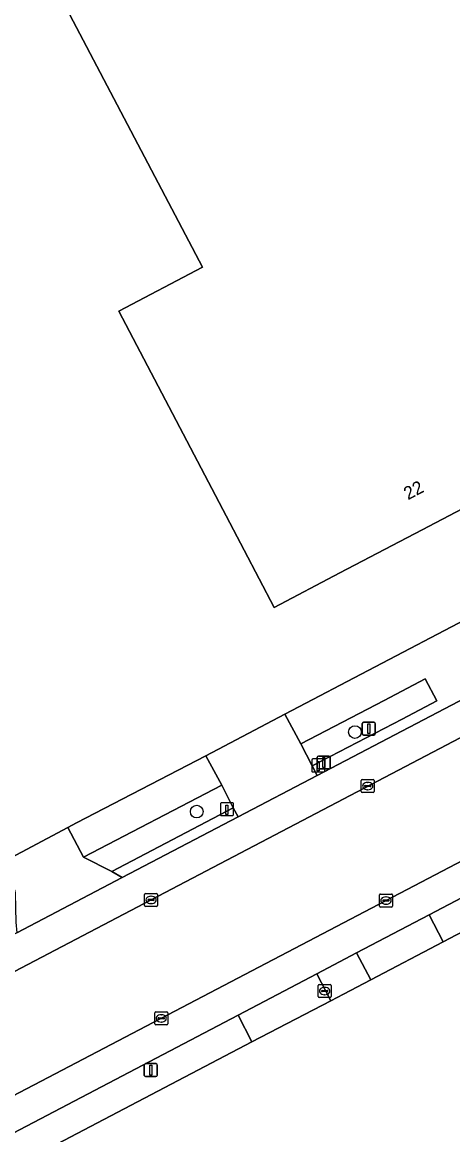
# Model space of a CAD drawing. Extents: x 157692 to 159674, y 381452 to 383291.
# Drawn here: x 158344.4 to 158377.6, y 381842.8 to 381928.6 of the extents above; entities that cross this region are included whole.
import ezdxf

# ---------------------------------------------------------------- set-up
doc = ezdxf.new("R2010")
doc.units = 0
for name, color, linetype in [('IMGEO_Boom', 7, 'Continuous'), ('IMGEO_Brandkraan', 7, 'Continuous'), ('IMGEO_Erf', 7, 'Continuous'), ('IMGEO_Groenvoorziening', 7, 'Continuous'), ('IMGEO_Kolk', 7, 'Continuous'), ('IMGEO_Lichtmast', 7, 'Continuous'), ('IMGEO_Paal', 7, 'Continuous'), ('IMGEO_Pand', 7, 'Continuous'), ('IMGEO_Pand_nummerreeks', 7, 'Continuous'), ('IMGEO_Parkeervlak_open', 7, 'Continuous'), ('IMGEO_Rijbaan_lokaal_gesloten', 7, 'Continuous'), ('IMGEO_Rijbaan_lokaal_open', 7, 'Continuous'), ('IMGEO_Verkeersbordpaal', 7, 'Continuous'), ('IMGEO_Voetpad_open', 7, 'Continuous')]:
    doc.layers.add(name, color=color, linetype=linetype)

msp = doc.modelspace()

# ---------------------------------------------------------------- linework, layer by layer
at = {"layer": 'IMGEO_Boom'}
for centre in [(158370.043, 381873.88), (158357.856, 381867.748)]:
    msp.add_circle(centre, 0.489, dxfattribs=at)
at = {"layer": 'IMGEO_Brandkraan'}
for p, q in [((158367.213, 381853.487), (158367.213, 381854.339)), ((158367.288, 381854.413), (158368.14, 381854.413)), ((158367.515, 381853.956), (158367.913, 381853.956)), ((158367.701, 381854.193), (158367.726, 381854.193)), ((158368.214, 381854.339), (158368.214, 381853.487)), ((158368.14, 381853.413), (158367.288, 381853.413)), ((158367.472, 381853.907), (158367.472, 381853.919)), ((158367.91, 381853.87), (158367.512, 381853.87)), ((158367.724, 381853.633), (158367.699, 381853.633)), ((158367.956, 381853.919), (158367.956, 381853.907))]:
    msp.add_line(p, q, dxfattribs=at)
for points in [[(158367.213, 381853.487), (158367.213, 381854.339)], [(158367.288, 381854.413), (158368.14, 381854.413)], [(158368.214, 381854.339), (158368.214, 381853.487)], [(158368.14, 381853.413), (158367.288, 381853.413)]]:
    msp.add_lwpolyline(points, dxfattribs=at)
for centre, radius, start, end in [((158367.29, 381854.337), 0.0765, 91.55205, 178.44795), ((158367.29, 381854.337), 0.0765, 91.55205, 178.44795), ((158367.512, 381853.916), 0.0403, 85.87752, 175.75265), ((158367.917, 381853.918), 0.0386, 1.73085, 96.63898), ((158368.138, 381854.337), 0.0765, 1.55205, 88.44795), ((158368.138, 381854.337), 0.0765, 1.55205, 88.44795), ((158367.29, 381853.489), 0.0765, 181.55205, 268.44795), ((158367.29, 381853.489), 0.0765, 181.55205, 268.44795), ((158367.509, 381853.906), 0.0366, 178.93798, 274.71019), ((158367.913, 381853.913), 0.043, 264.86636, 352.45326), ((158368.138, 381853.489), 0.0765, 271.55205, 358.44795), ((158368.138, 381853.489), 0.0765, 271.55205, 358.44795)]:
    msp.add_arc(centre, radius, start, end, dxfattribs=at)
for centre, major_axis, ratio, start_param, end_param in [((158367.7, 381853.913), (-0.387, 0.002), 0.722429, 4.712389, 7.853982), ((158367.725, 381853.913), (-0.39, 0.002), 0.717154, 1.570796, 4.712389)]:
    msp.add_ellipse(centre, major_axis=major_axis, ratio=ratio, start_param=start_param, end_param=end_param, dxfattribs=at)
at = {"layer": 'IMGEO_Erf'}
for points in [[(158388.245, 381896.308), (158375.217, 381889.463), (158368.891, 381886.139), (158363.822, 381883.475), (158361.501, 381887.904), (158351.845, 381906.325), (158358.302, 381909.71), (158344.12, 381936.701), (158326.37, 381927.38), (158323.288, 381933.25), (158316.019, 381929.433), (158324.588, 381970.857), (158366.026, 381962.599), (158372.005, 381951.251), (158371.05, 381950.754), (158385.081, 381924.026)], [(158217.316, 381839.906), (158270.263, 381825.792), (158286.558, 381834.286), (158292.839, 381837.605), (158310.343, 381846.755), (158316.773, 381850.116), (158323.795, 381853.778), (158342.759, 381863.76), (158347.941, 381866.531), (158348.596, 381866.872), (158358.563, 381872.057), (158364.635, 381875.26), (158392.478, 381889.849), (158400.12, 381893.872), (158401.991, 381894.865), (158408.14, 381898.064), (158436.465, 381912.9), (158441.823, 381915.706), (158446.378, 381918.092), (158458.186, 381924.156), (158466.161, 381928.413)], [(158416.142, 381764.387), (158441.975, 381777.745), (158461.034, 381788.171), (158500, 381809.488), (158502.7, 381810.965), (158517.225, 381818.911), (158502.7, 381848.284), (158500, 381853.744), (158473.086, 381908.164), (158468.009, 381905.516), (158408.054, 381874.141), (158402.221, 381871.049), (158376.84, 381857.708), (158371.263, 381854.776), (158369.169, 381853.676), (158368.188, 381853.16), (158362.112, 381850.005), (158326.367, 381831.251), (158320.477, 381828.192), (158299.749, 381817.336), (158293.835, 381814.232), (158289.45, 381811.892), (158283.086, 381808.549)]]:
    msp.add_lwpolyline(points, dxfattribs=at)
at = {"layer": 'IMGEO_Groenvoorziening'}
for points in [[(158376.362, 381876.274), (158375.465, 381877.969), (158372.304, 381876.312), (158365.865, 381872.972), (158366.751, 381871.28), (158373.694, 381874.863)], [(158351.326, 381863.129), (158360.665, 381868.04), (158359.785, 381869.784), (158349.146, 381864.225)]]:
    msp.add_lwpolyline(points, close=True, dxfattribs=at)
at = {"layer": 'IMGEO_Kolk'}
for p, q in [((158370.531, 381869.288), (158370.531, 381870.14)), ((158370.606, 381870.214), (158371.458, 381870.214)), ((158370.79, 381869.708), (158370.79, 381869.72)), ((158371.228, 381869.671), (158370.83, 381869.671)), ((158370.833, 381869.757), (158371.231, 381869.757)), ((158371.042, 381869.434), (158371.017, 381869.434)), ((158371.019, 381869.994), (158371.044, 381869.994)), ((158371.274, 381869.72), (158371.274, 381869.708)), ((158371.532, 381870.14), (158371.532, 381869.288)), ((158371.458, 381869.214), (158370.606, 381869.214)), ((158353.841, 381860.517), (158353.841, 381861.369)), ((158353.916, 381861.443), (158354.768, 381861.443)), ((158354.1, 381860.937), (158354.1, 381860.949)), ((158354.538, 381860.9), (158354.14, 381860.9)), ((158354.143, 381860.986), (158354.541, 381860.986)), ((158354.329, 381861.223), (158354.354, 381861.223)), ((158354.584, 381860.949), (158354.584, 381860.937)), ((158354.842, 381861.369), (158354.842, 381860.517)), ((158371.935, 381860.468), (158371.935, 381861.32)), ((158372.01, 381861.394), (158372.862, 381861.394)), ((158372.194, 381860.888), (158372.194, 381860.9)), ((158372.632, 381860.851), (158372.234, 381860.851)), ((158372.237, 381860.937), (158372.635, 381860.937)), ((158372.423, 381861.174), (158372.448, 381861.174)), ((158372.678, 381860.9), (158372.678, 381860.888)), ((158372.936, 381861.32), (158372.936, 381860.468)), ((158354.768, 381860.443), (158353.916, 381860.443)), ((158354.352, 381860.663), (158354.327, 381860.663)), ((158372.862, 381860.394), (158372.01, 381860.394)), ((158372.446, 381860.614), (158372.421, 381860.614)), ((158354.626, 381851.384), (158354.626, 381852.236)), ((158354.701, 381852.31), (158355.553, 381852.31)), ((158355.627, 381852.236), (158355.627, 381851.384)), ((158354.885, 381851.804), (158354.885, 381851.816)), ((158355.323, 381851.767), (158354.925, 381851.767)), ((158354.928, 381851.853), (158355.326, 381851.853)), ((158355.137, 381851.53), (158355.112, 381851.53)), ((158355.114, 381852.09), (158355.139, 381852.09)), ((158355.369, 381851.816), (158355.369, 381851.804)), ((158355.553, 381851.31), (158354.701, 381851.31))]:
    msp.add_line(p, q, dxfattribs=at)
for points in [[(158370.531, 381869.288), (158370.531, 381870.14)], [(158370.606, 381870.214), (158371.458, 381870.214)], [(158371.532, 381870.14), (158371.532, 381869.288)], [(158371.458, 381869.214), (158370.606, 381869.214)], [(158353.841, 381860.517), (158353.841, 381861.369)], [(158353.916, 381861.443), (158354.768, 381861.443)], [(158354.842, 381861.369), (158354.842, 381860.517)], [(158371.935, 381860.468), (158371.935, 381861.32)], [(158372.01, 381861.394), (158372.862, 381861.394)], [(158372.936, 381861.32), (158372.936, 381860.468)], [(158354.768, 381860.443), (158353.916, 381860.443)], [(158372.862, 381860.394), (158372.01, 381860.394)], [(158354.626, 381851.384), (158354.626, 381852.236)], [(158354.701, 381852.31), (158355.553, 381852.31)], [(158355.627, 381852.236), (158355.627, 381851.384)], [(158355.553, 381851.31), (158354.701, 381851.31)]]:
    msp.add_lwpolyline(points, dxfattribs=at)
for centre, radius, start, end in [((158370.608, 381870.138), 0.0765, 91.55205, 178.44795), ((158370.608, 381870.138), 0.0765, 91.55205, 178.44795), ((158370.83, 381869.717), 0.0403, 85.87752, 175.75265), ((158370.827, 381869.707), 0.0366, 178.93798, 274.71019), ((158371.231, 381869.714), 0.043, 264.86636, 352.45326), ((158371.235, 381869.719), 0.0386, 1.73085, 96.63898), ((158371.456, 381870.138), 0.0765, 1.55205, 88.44795), ((158371.456, 381870.138), 0.0765, 1.55205, 88.44795), ((158370.608, 381869.29), 0.0765, 181.55205, 268.44795), ((158370.608, 381869.29), 0.0765, 181.55205, 268.44795), ((158371.456, 381869.29), 0.0765, 271.55205, 358.44795), ((158371.456, 381869.29), 0.0765, 271.55205, 358.44795), ((158353.918, 381861.367), 0.0765, 91.55205, 178.44795), ((158353.918, 381861.367), 0.0765, 91.55205, 178.44795), ((158354.14, 381860.946), 0.0403, 85.87752, 175.75265), ((158354.137, 381860.936), 0.0366, 178.93798, 274.71019), ((158354.541, 381860.943), 0.043, 264.86636, 352.45326), ((158354.545, 381860.948), 0.0386, 1.73085, 96.63898), ((158354.766, 381861.367), 0.0765, 1.55205, 88.44795), ((158354.766, 381861.367), 0.0765, 1.55205, 88.44795), ((158372.012, 381861.318), 0.0765, 91.55205, 178.44795), ((158372.012, 381861.318), 0.0765, 91.55205, 178.44795), ((158372.234, 381860.897), 0.0403, 85.87752, 175.75265), ((158372.231, 381860.887), 0.0366, 178.93798, 274.71019), ((158372.635, 381860.894), 0.043, 264.86636, 352.45326), ((158372.639, 381860.899), 0.0386, 1.73085, 96.63898), ((158372.86, 381861.318), 0.0765, 1.55205, 88.44795), ((158372.86, 381861.318), 0.0765, 1.55205, 88.44795), ((158353.918, 381860.519), 0.0765, 181.55205, 268.44795), ((158353.918, 381860.519), 0.0765, 181.55205, 268.44795), ((158354.766, 381860.519), 0.0765, 271.55205, 358.44795), ((158354.766, 381860.519), 0.0765, 271.55205, 358.44795), ((158372.012, 381860.47), 0.0765, 181.55205, 268.44795), ((158372.012, 381860.47), 0.0765, 181.55205, 268.44795), ((158372.86, 381860.47), 0.0765, 271.55205, 358.44795), ((158372.86, 381860.47), 0.0765, 271.55205, 358.44795), ((158354.703, 381852.234), 0.0765, 91.55205, 178.44795), ((158354.703, 381852.234), 0.0765, 91.55205, 178.44795), ((158355.551, 381852.234), 0.0765, 1.55205, 88.44795), ((158355.551, 381852.234), 0.0765, 1.55205, 88.44795), ((158354.703, 381851.386), 0.0765, 181.55205, 268.44795), ((158354.703, 381851.386), 0.0765, 181.55205, 268.44795), ((158354.925, 381851.813), 0.0403, 85.87752, 175.75265), ((158354.922, 381851.803), 0.0366, 178.93798, 274.71019), ((158355.326, 381851.81), 0.043, 264.86636, 352.45326), ((158355.33, 381851.815), 0.0386, 1.73085, 96.63898), ((158355.551, 381851.386), 0.0765, 271.55205, 358.44795), ((158355.551, 381851.386), 0.0765, 271.55205, 358.44795)]:
    msp.add_arc(centre, radius, start, end, dxfattribs=at)
for centre, major_axis, ratio, start_param, end_param in [((158371.018, 381869.714), (-0.387, 0.002), 0.722429, 4.712389, 7.853982), ((158371.043, 381869.714), (-0.39, 0.002), 0.717154, 1.570796, 4.712389), ((158354.328, 381860.943), (-0.387, 0.002), 0.722429, 4.712389, 7.853982), ((158354.353, 381860.943), (-0.39, 0.002), 0.717154, 1.570796, 4.712389), ((158372.422, 381860.894), (-0.387, 0.002), 0.722429, 4.712389, 7.853982), ((158372.447, 381860.894), (-0.39, 0.002), 0.717154, 1.570796, 4.712389), ((158355.113, 381851.81), (-0.387, 0.002), 0.722429, 4.712389, 7.853982), ((158355.138, 381851.81), (-0.39, 0.002), 0.717154, 1.570796, 4.712389)]:
    msp.add_ellipse(centre, major_axis=major_axis, ratio=ratio, start_param=start_param, end_param=end_param, dxfattribs=at)
at = {"layer": 'IMGEO_Lichtmast'}
for p, q in [((158367.242, 381872.031), (158368.032, 381872.031)), ((158368.032, 381872.031), (158367.242, 381872.031)), ((158367.142, 381871.131), (158367.142, 381871.931)), ((158367.142, 381871.931), (158367.142, 381871.131)), ((158368.132, 381871.931), (158368.132, 381871.131)), ((158368.132, 381871.131), (158368.132, 381871.931)), ((158368.032, 381871.031), (158367.242, 381871.031)), ((158367.242, 381871.031), (158368.032, 381871.031)), ((158353.82, 381847.42), (158353.82, 381848.22)), ((158353.82, 381848.22), (158353.82, 381847.42)), ((158353.92, 381848.32), (158354.71, 381848.32)), ((158354.71, 381848.32), (158353.92, 381848.32)), ((158354.81, 381848.22), (158354.81, 381847.42)), ((158354.81, 381847.42), (158354.81, 381848.22)), ((158354.71, 381847.32), (158353.92, 381847.32)), ((158353.92, 381847.32), (158354.71, 381847.32))]:
    msp.add_line(p, q, dxfattribs=at)
for points in [[(158367.562, 381871.906), (158367.712, 381871.906), (158367.712, 381871.156), (158367.562, 381871.156), (158367.562, 381871.906)], [(158354.24, 381848.195), (158354.39, 381848.195), (158354.39, 381847.445), (158354.24, 381847.445), (158354.24, 381848.195)]]:
    msp.add_lwpolyline(points, dxfattribs=at)
for centre, start, end in [((158367.242, 381871.931), 90, 180), ((158367.242, 381871.931), 90, 180), ((158368.032, 381871.931), 0, 90), ((158368.032, 381871.931), 360, 90), ((158367.242, 381871.131), 180, 270), ((158367.242, 381871.131), 180, 270), ((158368.032, 381871.131), 270, 0), ((158368.032, 381871.131), 270, 0), ((158353.92, 381848.22), 90, 180), ((158353.92, 381848.22), 90, 180), ((158354.71, 381848.22), 0, 90), ((158354.71, 381848.22), 360, 90), ((158353.92, 381847.42), 180, 270), ((158353.92, 381847.42), 180, 270), ((158354.71, 381847.42), 270, 0), ((158354.71, 381847.42), 270, 0)]:
    msp.add_arc(centre, 0.1, start, end, dxfattribs=at)
at = {"layer": 'IMGEO_Paal'}
for p, q in [((158366.723, 381871.718), (158366.723, 381870.877)), ((158366.723, 381871.718), (158366.723, 381870.877)), ((158367.639, 381871.802), (158366.798, 381871.802)), ((158367.639, 381871.802), (158366.798, 381871.802)), ((158367.723, 381870.886), (158367.723, 381871.727)), ((158367.723, 381870.886), (158367.723, 381871.727)), ((158366.807, 381870.802), (158367.648, 381870.802)), ((158366.807, 381870.802), (158367.648, 381870.802)), ((158359.683, 381868.351), (158359.683, 381867.51)), ((158359.683, 381868.351), (158359.683, 381867.51)), ((158360.599, 381868.435), (158359.758, 381868.435)), ((158360.599, 381868.435), (158359.758, 381868.435)), ((158360.683, 381867.519), (158360.683, 381868.36)), ((158360.683, 381867.519), (158360.683, 381868.36)), ((158359.767, 381867.435), (158360.608, 381867.435)), ((158359.767, 381867.435), (158360.608, 381867.435))]:
    msp.add_line(p, q, dxfattribs=at)
for points in [[(158367.138, 381871.615), (158367.298, 381871.615), (158367.298, 381870.882), (158367.138, 381870.882), (158367.138, 381871.615)], [(158360.098, 381868.248), (158360.258, 381868.248), (158360.258, 381867.515), (158360.098, 381867.515), (158360.098, 381868.248)]]:
    msp.add_lwpolyline(points, dxfattribs=at)
for centre, start, end in [((158366.801, 381871.724), 92.4484, 184.28452), ((158366.801, 381871.724), 92.4484, 184.28452), ((158367.645, 381871.724), 2.4484, 94.28452), ((158367.645, 381871.724), 2.4484, 94.28452), ((158366.801, 381870.88), 182.4484, 274.28452), ((158366.801, 381870.88), 182.4484, 274.28452), ((158367.645, 381870.88), 272.4484, 4.28452), ((158367.645, 381870.88), 272.4484, 4.28452), ((158359.761, 381868.357), 92.4484, 184.28452), ((158359.761, 381868.357), 92.4484, 184.28452), ((158360.605, 381868.357), 2.4484, 94.28452), ((158360.605, 381868.357), 2.4484, 94.28452), ((158359.761, 381867.513), 182.4484, 274.28452), ((158359.761, 381867.513), 182.4484, 274.28452), ((158360.605, 381867.513), 272.4484, 4.28452), ((158360.605, 381867.513), 272.4484, 4.28452)]:
    msp.add_arc(centre, 0.0779, start, end, dxfattribs=at)
at = {"layer": 'IMGEO_Pand'}
msp.add_lwpolyline([(158385.081, 381924.026), (158371.05, 381950.754), (158372.005, 381951.251), (158366.026, 381962.599), (158324.588, 381970.857), (158316.019, 381929.433), (158323.288, 381933.25), (158326.37, 381927.38), (158344.12, 381936.701), (158358.302, 381909.71), (158351.845, 381906.325), (158361.501, 381887.904), (158363.822, 381883.475), (158368.891, 381886.139), (158375.217, 381889.463), (158388.245, 381896.308)], dxfattribs=at)
at = {"layer": 'IMGEO_Parkeervlak_open'}
for points in [[(158457.404, 381917.836), (158454, 381916.055), (158450.723, 381914.341), (158444.327, 381910.99), (158438.977, 381908.187), (158410.471, 381893.25), (158404.483, 381890.119), (158402.628, 381889.151), (158394.949, 381885.105), (158367.135, 381870.529), (158361.052, 381867.333), (158352.126, 381862.671), (158343.994, 381858.396), (158326.305, 381849.121), (158319.191, 381845.384), (158295.421, 381832.972), (158289.047, 381829.577), (158275.611, 381822.585), (158273.839, 381821.727), (158272.432, 381821.141), (158272.056, 381820.902), (158271.811, 381820.664), (158269.983, 381818.259)], [(158275.635, 381819.726), (158303.732, 381834.411), (158354.339, 381860.942), (158456.473, 381914.515)], [(158465.398, 381909.602), (158462.964, 381908.32), (158340.401, 381844.12), (158287.161, 381816.195)], [(158292.185, 381815.989), (158292.781, 381816.313), (158298.654, 381819.389), (158319.401, 381830.234), (158325.276, 381833.312), (158361.043, 381852.051), (158367.101, 381855.247), (158370.176, 381856.864), (158375.752, 381859.796), (158401.117, 381873.133), (158406.97, 381876.204), (158463.062, 381905.633)]]:
    msp.add_lwpolyline(points, dxfattribs=at)
at = {"layer": 'IMGEO_Rijbaan_lokaal_gesloten'}
for points in [[(158462.964, 381908.32), (158465.398, 381909.602), (158465.751, 381909.788), (158471.08, 381912.561), (158472.817, 381913.475), (158469.812, 381921.671), (158469.469, 381921.453), (158467.76, 381920.403), (158467.185, 381920.095), (158464.206, 381918.501), (158463.074, 381917.968), (158462.356, 381917.596), (158458.149, 381915.386), (158456.473, 381914.515), (158354.339, 381860.942), (158303.732, 381834.411), (158275.635, 381819.726)], [(158280.869, 381812.874), (158287.161, 381816.195), (158340.401, 381844.12), (158462.964, 381908.32)]]:
    msp.add_lwpolyline(points, dxfattribs=at)
at = {"layer": 'IMGEO_Rijbaan_lokaal_open'}
for points in [[(158365.865, 381872.972), (158364.635, 381875.26), (158358.563, 381872.057), (158359.785, 381869.784), (158360.665, 381868.04), (158361.052, 381867.333), (158367.135, 381870.529), (158366.751, 381871.28)], [(158349.146, 381864.225), (158347.941, 381866.531), (158342.759, 381863.76), (158343.852, 381861.677), (158343.859, 381861.437), (158343.927, 381859.236), (158343.994, 381858.396), (158352.126, 381862.671), (158351.326, 381863.129)]]:
    msp.add_lwpolyline(points, close=True, dxfattribs=at)
at = {"layer": 'IMGEO_Verkeersbordpaal'}
for p, q in [((158370.61, 381873.738), (158370.61, 381874.538)), ((158370.61, 381874.538), (158370.61, 381873.738)), ((158370.71, 381874.638), (158371.5, 381874.638)), ((158371.5, 381874.638), (158370.71, 381874.638)), ((158371.6, 381874.538), (158371.6, 381873.738)), ((158371.6, 381873.738), (158371.6, 381874.538)), ((158371.5, 381873.638), (158370.71, 381873.638)), ((158370.71, 381873.638), (158371.5, 381873.638))]:
    msp.add_line(p, q, dxfattribs=at)
msp.add_lwpolyline([(158371.03, 381874.513), (158371.18, 381874.513), (158371.18, 381873.763), (158371.03, 381873.763), (158371.03, 381874.513)], dxfattribs=at)
for centre, start, end in [((158370.71, 381874.538), 90, 180), ((158370.71, 381874.538), 90, 180), ((158371.5, 381874.538), 0, 90), ((158371.5, 381874.538), 360, 90), ((158370.71, 381873.738), 180, 270), ((158370.71, 381873.738), 180, 270), ((158371.5, 381873.738), 270, 0), ((158371.5, 381873.738), 270, 0)]:
    msp.add_arc(centre, 0.1, start, end, dxfattribs=at)
at = {"layer": 'IMGEO_Voetpad_open'}
for points in [[(158378.313, 381879.471), (158381.86, 381881.318), (158393.672, 381887.557), (158392.478, 381889.849), (158364.635, 381875.26), (158365.865, 381872.972), (158372.304, 381876.312), (158375.465, 381877.969), (158376.362, 381876.274), (158373.694, 381874.863), (158366.751, 381871.28), (158367.135, 381870.529), (158394.949, 381885.105), (158394.579, 381885.816), (158381.988, 381879.236), (158379.221, 381877.781)], [(158375.752, 381859.796), (158376.84, 381857.708), (158402.221, 381871.049), (158401.117, 381873.133)], [(158359.785, 381869.784), (158358.563, 381872.057), (158348.596, 381866.872), (158347.941, 381866.531), (158349.146, 381864.225)], [(158361.052, 381867.333), (158360.665, 381868.04), (158351.326, 381863.129), (158352.126, 381862.671)], [(158370.176, 381856.864), (158371.263, 381854.776), (158376.84, 381857.708), (158375.752, 381859.796)], [(158369.169, 381853.676), (158371.263, 381854.776), (158370.176, 381856.864), (158367.101, 381855.247), (158368.188, 381853.16)], [(158361.043, 381852.051), (158362.112, 381850.005), (158368.188, 381853.16), (158367.101, 381855.247)], [(158325.276, 381833.312), (158326.367, 381831.251), (158362.112, 381850.005), (158361.043, 381852.051)]]:
    msp.add_lwpolyline(points, close=True, dxfattribs=at)

# ---------------------------------------------------------------- texts
at = {"layer": 'IMGEO_Pand_nummerreeks'}
msp.add_text('22', height=1, rotation=27.71956, dxfattribs=at).set_placement((158374.127, 381891.737))

doc.saveas('drawing.dxf')
